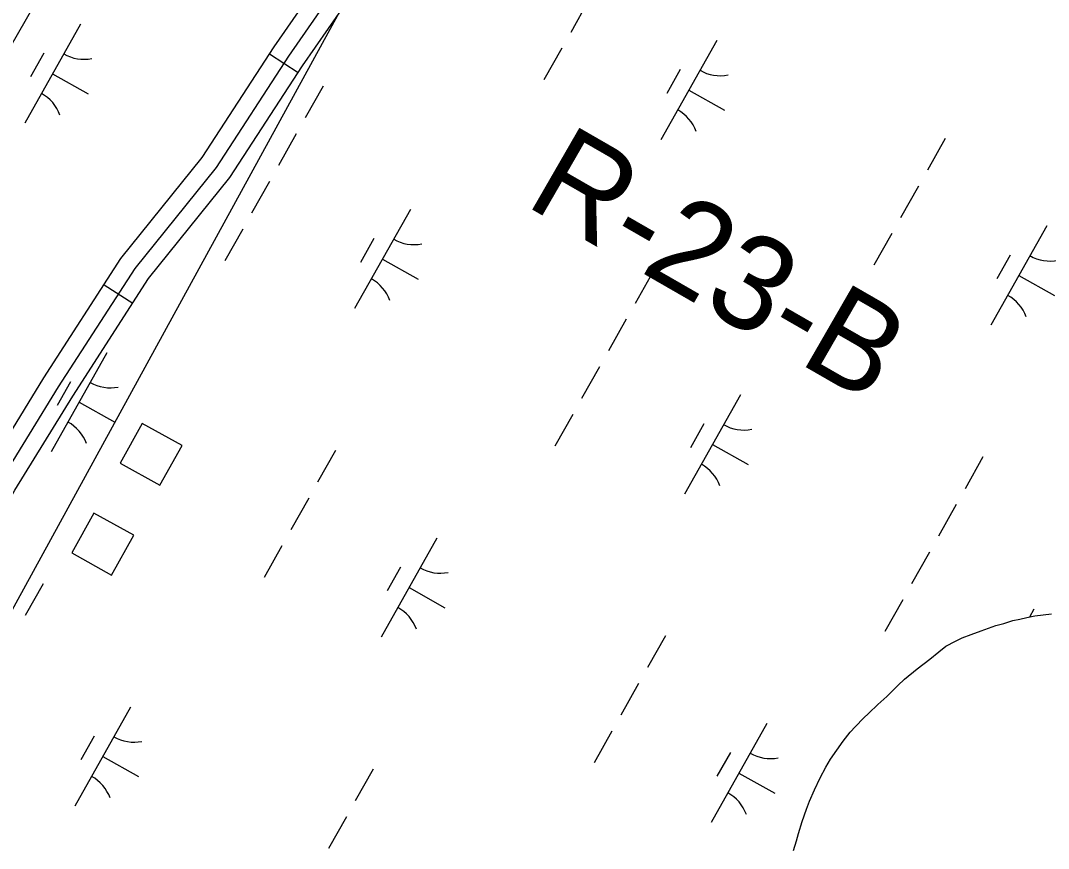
# Model space of a CAD drawing. Extents: x 3913936 to 3933962, y 195330 to 217741.
# Drawn here: x 3926769.2 to 3927220.9, y 205117.9 to 205481.9 of the extents above; entities that cross this region are included whole.
import ezdxf

# ---------------------------------------------------------------- set-up
doc = ezdxf.new("R2010")
doc.units = 0
for name, color, linetype in [('V-BLDG-OTLN', 7, 'Continuous'), ('V-RIVR-RANG-IDEN', 7, 'Continuous'), ('V-ROAD-CNTR', 7, 'Continuous'), ('V-TOPO-SHOR', 7, 'Continuous'), ('V-UTIL-LINE', 7, 'Continuous'), ('V-WETL-SWMP', 7, 'Continuous')]:
    doc.layers.add(name, color=color, linetype=linetype)

msp = doc.modelspace()

# ---------------------------------------------------------------- linework, layer by layer
at = {"layer": 'V-BLDG-OTLN'}
for points in [[(3926822.69, 205304.81), (3926812.98, 205287.33), (3926830.46, 205277.61), (3926840.18, 205295.1)], [(3926801.42, 205265.32), (3926791.71, 205247.84), (3926809.19, 205238.12), (3926818.9, 205255.61)]]:
    msp.add_lwpolyline(points, close=True, dxfattribs=at)
at = {"layer": 'V-ROAD-CNTR'}
for p, q in [((3926878.63, 205467.26), (3926891.21, 205459.08)), ((3926805.87, 205365.78), (3926818.47, 205357.65))]:
    msp.add_line(p, q, dxfattribs=at)
for points in [[(3926727.99, 205237.11), (3926753.79, 205283.01), (3926779.44, 205324.79), (3926813.29, 205377.3), (3926849.04, 205421.76), (3926880.66, 205470.37), (3926915.04, 205520.04), (3926947.31, 205566.03), (3926981.2, 205626.32), (3927031.37, 205707.91), (3927091, 205810.16), (3927148.97, 205894.08)], [(3927155.14, 205889.81), (3927097.34, 205806.13), (3927037.81, 205704.06), (3926987.67, 205622.52), (3926953.67, 205562.03), (3926921.2, 205515.75), (3926886.88, 205466.19), (3926855.13, 205417.35), (3926819.38, 205372.9), (3926785.79, 205320.79), (3926760.26, 205279.21), (3926734.53, 205233.43)], [(3926741.06, 205229.76), (3926766.73, 205275.41), (3926792.13, 205316.8), (3926825.47, 205368.51), (3926861.21, 205412.95), (3926893.11, 205462.01), (3926927.35, 205511.46), (3926960.02, 205558.03), (3926994.14, 205618.72), (3927044.24, 205700.2), (3927103.67, 205802.1), (3927161.31, 205885.55)]]:
    msp.add_lwpolyline(points, dxfattribs=at)
at = {"layer": 'V-TOPO-SHOR'}
msp.add_lwpolyline([(3927108.84, 205117.02), (3927110.11, 205121.23), (3927111, 205124.39), (3927112.66, 205129.78), (3927114.58, 205135.18), (3927115.85, 205138.61), (3927118.04, 205143.61), (3927120.62, 205148.89), (3927123.06, 205153.64), (3927125.13, 205157.07), (3927127.85, 205161.03), (3927130.7, 205165.12), (3927133.82, 205168.96), (3927136.02, 205171.48), (3927139.66, 205175.18), (3927142.01, 205177.31), (3927145.91, 205181.15), (3927149.81, 205184.73), (3927154.75, 205189.5), (3927157.61, 205192.28), (3927163.21, 205196.93), (3927168.69, 205201.18), (3927172.73, 205204.37), (3927175.72, 205206.76), (3927180.03, 205209.03), (3927182.91, 205210.5), (3927186.96, 205211.98), (3927191.28, 205213.6), (3927194.55, 205214.81), (3927197.82, 205215.89), (3927201.22, 205216.84), (3927205.28, 205218.06), (3927208.29, 205218.74), (3927211.44, 205219.43), (3927214.97, 205220.12), (3927218.51, 205220.68), (3927222.18, 205221.1)], dxfattribs=at)
at = {"layer": 'V-UTIL-LINE'}
for points in [[(3922259.35, 198607.65), (3922481.8, 198996.51), (3922891.23, 199568.37), (3923401.91, 200205.88), (3924391.34, 201632.88), (3925141.51, 202100.49), (3925635.89, 202689.84), (3926060.57, 203224.55), (3926266.36, 203722.12), (3926398.76, 204373.14), (3926759.45, 205211.96), (3927229.53, 206070.79), (3927602.51, 206766.2), (3928031.78, 207586.17)], [(3927650.36, 207012.75), (3925143.73, 202648.17), (3924419.49, 201771.61), (3924393.53, 201817.62)]]:
    msp.add_lwpolyline(points, dxfattribs=at)
at = {"layer": 'V-WETL-SWMP'}
for p, q in [((3927018.78, 205490.68), (3927010.94, 205476.74)), ((3926795.52, 205480.34), (3926771.01, 205436.75)), ((3927075.12, 205473.12), (3927050.62, 205429.53)), ((3926779.48, 205467.56), (3926773.6, 205457.1)), ((3927007.02, 205469.76), (3926999.18, 205455.81)), ((3926783.26, 205458.55), (3926798.96, 205449.73)), ((3927059.08, 205460.34), (3927053.2, 205449.88)), ((3926902.11, 205453.02), (3926894.27, 205439.08)), ((3927062.87, 205451.33), (3927078.56, 205442.51)), ((3926890.35, 205432.1), (3926882.51, 205418.16)), ((3927175.54, 205430.09), (3927167.7, 205416.15)), ((3926878.59, 205411.18), (3926870.75, 205397.23)), ((3927163.78, 205409.17), (3927155.94, 205395.23)), ((3926940.51, 205398.83), (3926916.01, 205355.24)), ((3926866.83, 205390.26), (3926858.99, 205376.31)), ((3927220.11, 205391.61), (3927195.61, 205348.02)), ((3926924.48, 205386.05), (3926918.6, 205375.59)), ((3927152.02, 205388.25), (3927144.18, 205374.31)), ((3926928.26, 205377.04), (3926943.95, 205368.22)), ((3927204.08, 205378.83), (3927198.2, 205368.37)), ((3927047.11, 205371.51), (3927039.26, 205357.57)), ((3927207.86, 205369.82), (3927223.55, 205361)), ((3927035.34, 205350.59), (3927027.5, 205336.65)), ((3926807.15, 205335.87), (3926782.64, 205292.28)), ((3927023.58, 205329.67), (3927015.74, 205315.73)), ((3926791.11, 205323.09), (3926785.23, 205312.63)), ((3926794.89, 205314.08), (3926810.59, 205305.26)), ((3927085.51, 205317.32), (3927061.01, 205273.73)), ((3927011.82, 205308.75), (3927003.98, 205294.8)), ((3927069.48, 205304.54), (3927063.59, 205294.08)), ((3927073.26, 205295.53), (3927088.95, 205286.71)), ((3926907.57, 205292.84), (3926899.73, 205278.9)), ((3927192.1, 205290.01), (3927184.26, 205276.06)), ((3926895.81, 205271.92), (3926887.97, 205257.98)), ((3927180.34, 205269.08), (3927172.5, 205255.14)), ((3926952.14, 205254.36), (3926927.64, 205210.77)), ((3926884.05, 205251), (3926876.21, 205237.06)), ((3927168.58, 205248.16), (3927160.74, 205234.22)), ((3926936.11, 205241.58), (3926930.23, 205231.12)), ((3926779.13, 205234.26), (3926771.29, 205220.32)), ((3926939.89, 205232.57), (3926955.58, 205223.75)), ((3927156.82, 205227.24), (3927148.98, 205213.29)), ((3927214.47, 205223.03), (3927212.57, 205219.65)), ((3927052.56, 205211.34), (3927044.72, 205197.39)), ((3927040.8, 205190.41), (3927032.96, 205176.47)), ((3926817.54, 205180.07), (3926793.04, 205136.48)), ((3927029.04, 205169.49), (3927021.2, 205155.55)), ((3927097.14, 205172.85), (3927072.64, 205129.27)), ((3926801.5, 205167.29), (3926795.62, 205156.83)), ((3927081.1, 205160.07), (3927075.22, 205149.61)), ((3926805.29, 205158.28), (3926820.98, 205149.46)), ((3926924.13, 205152.76), (3926916.29, 205138.81)), ((3927084.89, 205151.06), (3927100.58, 205142.24)), ((3926912.37, 205131.83), (3926904.53, 205117.89))]:
    msp.add_line(p, q, dxfattribs=at)
msp.add_lwpolyline([(3927108.84, 205117.02), (3927110.11, 205121.23), (3927111, 205124.39), (3927112.66, 205129.78), (3927114.58, 205135.18), (3927115.86, 205138.61), (3927118.04, 205143.61), (3927120.62, 205148.89), (3927123.06, 205153.64), (3927125.13, 205157.07), (3927127.85, 205161.03), (3927130.7, 205165.12), (3927133.82, 205168.96), (3927136.02, 205171.48), (3927139.66, 205175.18), (3927142.01, 205177.31), (3927145.91, 205181.15), (3927149.81, 205184.73), (3927154.75, 205189.5), (3927157.62, 205192.28), (3927163.22, 205196.93), (3927168.69, 205201.18), (3927172.73, 205204.37), (3927175.72, 205206.76), (3927180.03, 205209.03), (3927182.91, 205210.5), (3927186.96, 205211.98), (3927191.28, 205213.6), (3927194.55, 205214.81), (3927197.82, 205215.89), (3927201.22, 205216.84), (3927205.28, 205218.06), (3927208.29, 205218.74), (3927211.44, 205219.43), (3927214.97, 205220.12), (3927218.51, 205220.68), (3927222.18, 205221.1)], dxfattribs=at)
for centre, start, end in [((3926797.01, 205482.51), 239.8861, 281.4297), ((3927076.61, 205475.29), 239.8861, 281.4297), ((3926769.94, 205434.35), 19.8861, 61.4297), ((3927049.54, 205427.13), 19.8861, 61.4297), ((3926942, 205401), 239.8861, 281.4297), ((3927221.61, 205393.78), 239.8861, 281.4297), ((3926914.93, 205352.84), 19.8861, 61.4297), ((3927194.54, 205345.62), 19.8861, 61.4297), ((3926808.64, 205338.04), 239.8861, 281.4297), ((3926781.57, 205289.88), 19.8861, 61.4297), ((3927087, 205319.49), 239.8861, 281.4297), ((3927059.93, 205271.33), 19.8861, 61.4297), ((3926953.63, 205256.53), 239.8861, 281.4297), ((3926926.56, 205208.37), 19.8861, 61.4297), ((3926819.03, 205182.24), 239.8861, 281.4297), ((3927098.63, 205175.02), 239.8861, 281.4297), ((3926791.96, 205134.08), 19.8861, 61.4297), ((3927071.56, 205126.86), 19.8861, 61.4297)]:
    msp.add_arc(centre, 17.62, start, end, dxfattribs=at)

# ---------------------------------------------------------------- texts
at = {"layer": 'V-RIVR-RANG-IDEN'}
msp.add_text('R-23-B', height=41.5, rotation=330.0459, dxfattribs=at).set_placement((3926990.09, 205401.07))

doc.saveas('drawing.dxf')
